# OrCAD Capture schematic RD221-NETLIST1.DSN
size A3
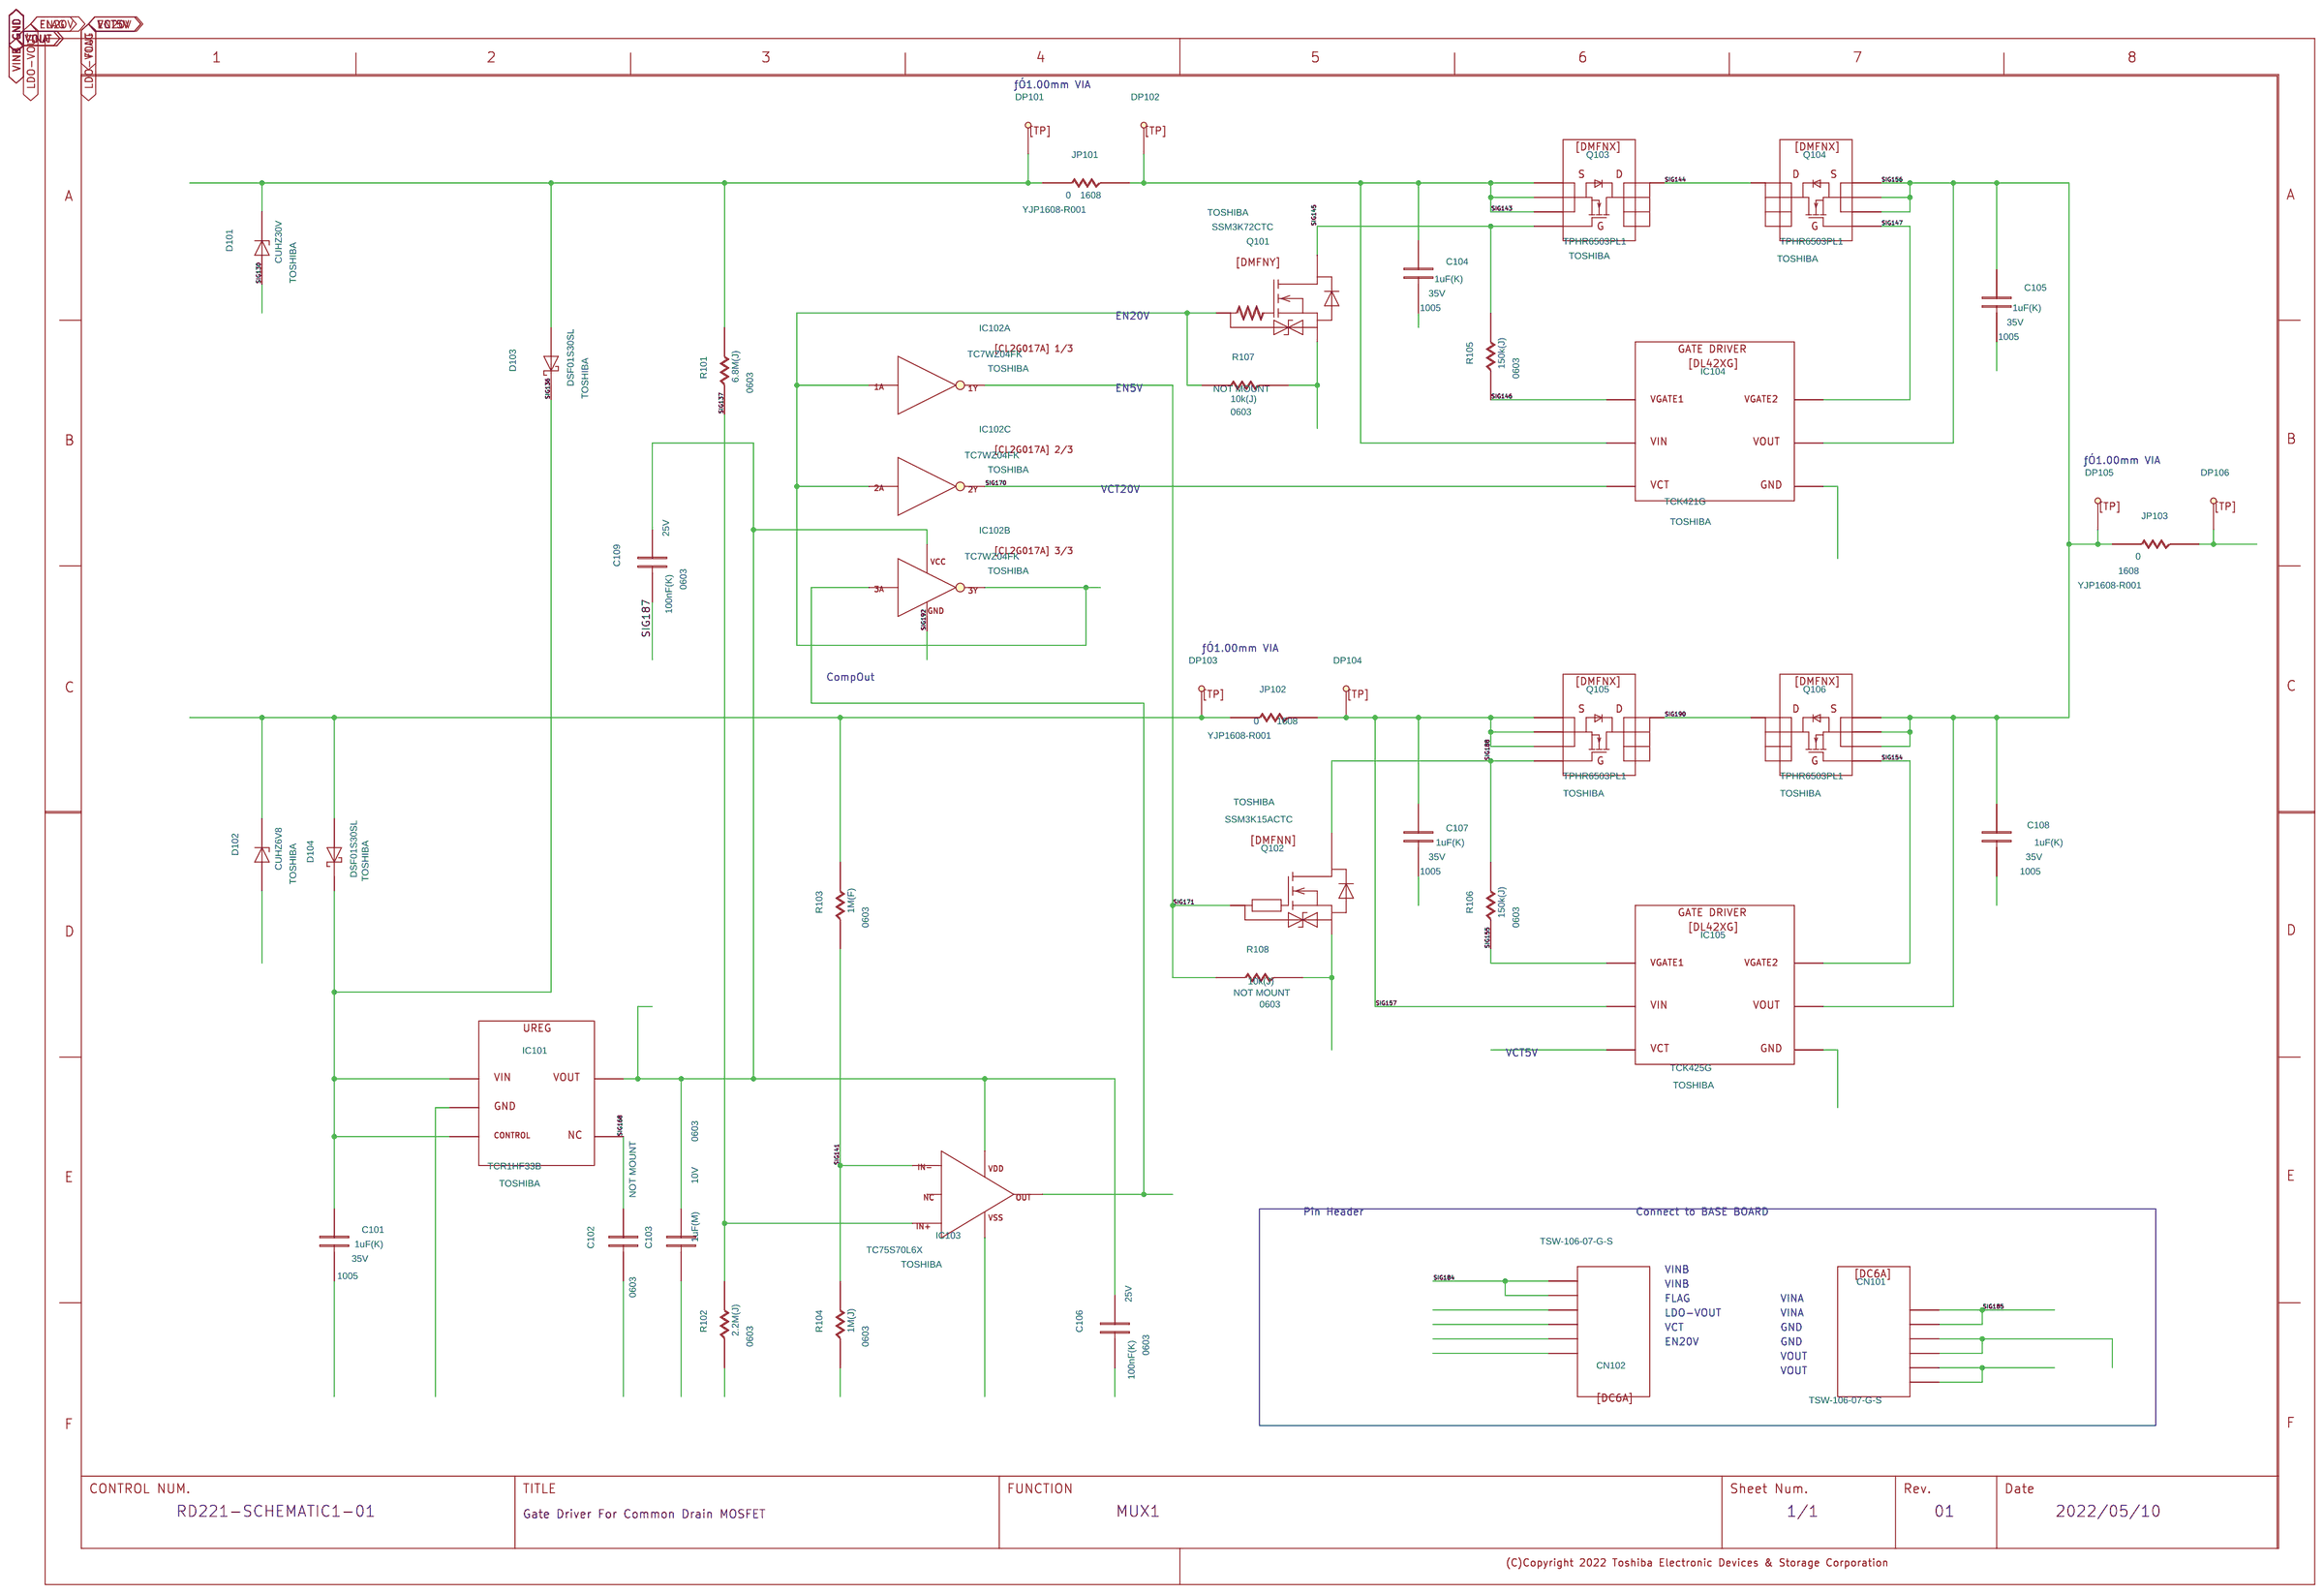
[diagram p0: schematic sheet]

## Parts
C101  DC
C102  DC
C103  DC
C104  DC
C105  DC
C106  DC
C107  DC
C108  DC
C109  DC
CN101  DC6A
CN102  DC6A
D101  DZD
D102  DZD
D103  DSBD
D104  DSBD
DP101  DTP
DP102  DTP
DP103  DTP
DP104  DTP
DP105  DTP
DP106  DTP
IC101  DL1HFXX
IC102  TC7WZ04FK_1  (sections A,B,C)
IC103  TC75S70L6X
IC104  DL42XG
IC105  DL42XG
JP101  DR
JP102  DR
JP103  DR
Q101  DMFNY
Q102  DMFNN
Q103  DMFNX
Q104  DMFNX
Q105  DMFNX
Q106  DMFNX
R101  DR
R102  DR
R103  DR
R104  DR
R105  DR
R106  DR
R107  DR
R108  DR
U?#1  WAKU_DEF100

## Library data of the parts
C101 C104 C105 C107 C108 = DC: COMP: DP0000016125; COMPONENTNAME: DP0000016125_package; FUNCN: DP0000016125; GCOUNT: 1; MAXGCOUNT: 1; OUMEPARTTYPE: C; SIZECODESMD: 1005; VAL1: 1uF(K); VAL2: 35V; VAL3: GRM155R6YA105KE11D
C102 = DC: COMP: DP0007093000; COMPONENTNAME: DP0007093000_package; FUNCN: DP0007093000; GCOUNT: 1; MAXGCOUNT: 1; NOTMOUNT: NOT MOUNT; OUMEPARTTYPE: C; SIZECODESMD: 0603; VAL1: 1uF(M); VAL2: 10V; VAL3: GRM033R61A105ME15D
C103 = DC: COMP: DP0007093000; COMPONENTNAME: DP0007093000_package; FUNCN: DP0007093000; GCOUNT: 1; MAXGCOUNT: 1; OUMEPARTTYPE: C; SIZECODESMD: 0603; VAL1: 1uF(M); VAL2: 10V; VAL3: GRM033R61A105ME15D
C106 C109 = DC: COMP: DP0000015403; COMPONENTNAME: DP0000015403_package; FUNCN: DP0000015403; GCOUNT: 1; MAXGCOUNT: 1; OUMEPARTTYPE: C; SIZECODESMD: 0603; VAL1: 100nF(K); VAL2: 25V; VAL3: GRM033R61E104KE14D
CN101 CN102 = DC6A: COMP: DP0010563000; COMPONENTNAME: DP0010563000_package; FUNCN: DP0010563000; GCOUNT: 1; MAXGCOUNT: 1; OUMEPARTTYPE: CN; VAL3: TSW-106-07-G-S
D101 = DZD: COMP: DP0010557000; COMPONENTNAME: DP0010557000_package; FUNCN: DP0010557000; GCOUNT: 1; MAXGCOUNT: 1; OUMEPARTTYPE: D; USERCOMPTEXT3: TOSHIBA; VAL1: CUHZ30V; VAL3: CUHZ30V
D102 = DZD: COMP: DP0010558000; COMPONENTNAME: DP0010558000_package; FUNCN: DP0010558000; GCOUNT: 1; MAXGCOUNT: 1; OUMEPARTTYPE: D; USERCOMPTEXT3: TOSHIBA; VAL1: CUHZ6V8; VAL3: CUHZ6V8
D103 D104 = DSBD: COMP: DP0010560000; COMPONENTNAME: DP0010560000_package; FUNCN: DP0010560000; GCOUNT: 1; MAXGCOUNT: 1; OUMEPARTTYPE: D; USERCOMPTEXT3: TOSHIBA; VAL1: DSF01S30SL; VAL3: DSF01S30SL
DP101-DP106 = DTP: COMP: DP9000817000; COMPONENTNAME: DP9000817000_package; FUNCN: DP9000817000; GCOUNT: 1; MAXGCOUNT: 1; NOTMOUNT: NOT MOUNT; OUMEPARTTYPE: TP
IC101 = DL1HFXX: COMP: DP0010559000; COMPONENTNAME: DP0010559000_package; FUNCN: DP0010559000; GCOUNT: 1; MAXGCOUNT: 1; OUMEPARTTYPE: IC; SAVEAREA0: -37394,-7797,68343,35643; SAVECOUNT: 26; UPDATEDATE: 2021/11/24; UPDATETIME: 10:48:25; UPDATEUSER: w90028dm; USERCOMPTEXT3: TOSHIBA; VAL1: TCR1HF33B; VAL3: TCR1HF33B
IC102 = TC7WZ04FK_1: COMP: DP0001429000; CaptureCellPackProp: TC7WZ04FK_1A; FUNCN: DP0001429000_1; USERCOMPTEXT3: TOSHIBA; VAL1: TC7WZ04FK; VAL3: TC7WZ04FK
IC103 = TC75S70L6X: COMP: DP0010561000; COMPONENTNAME: DP0010561000; FUNCN: DP0010561000; USERCOMPTEXT3: TOSHIBA
IC104 = DL42XG: COMP: DP0010555000; COMPONENTNAME: DP0010555000_package; FUNCN: DP0010555000; GCOUNT: 1; MAXGCOUNT: 1; OUMEPARTTYPE: IC; SAVEAREA0: 0,-2569,38100,25362; UPDATEDATE: 2021/11/09; UPDATETIME: 14:52:41; UPDATEUSER: t5459927; USERCOMPTEXT3: TOSHIBA; VAL1: TCK421G; VAL3: TCK421G
IC105 = DL42XG: COMP: DP0010556000; COMPONENTNAME: DP0010556000_package; FUNCN: DP0010556000; GCOUNT: 1; MAXGCOUNT: 1; OUMEPARTTYPE: IC; SAVEAREA0: -5715,0,43876,22860; UPDATEDATE: 2021/11/09; UPDATETIME: 13:49:24; UPDATEUSER: t5459927; USERCOMPTEXT3: TOSHIBA; VAL1: TCK425G; VAL3: TCK425G
JP101-JP103 = DR: COMP: DP0001376000; COMPCOMMENT: 0; COMPONENTNAME: DP0001376000_package; FUNCN: DP0001376000; GCOUNT: 1; MAXGCOUNT: 1; OUMEPARTTYPE: R; SIZECODESMD: 1608; VAL1: 200u(X); VAL2: 30mW; VAL3: YJP1608-R001
Q101 = DMFNY: COMP: DP0010564000; COMPONENTNAME: DP0010564000_package; FUNCN: DP0010564000; GCOUNT: 1; MAXGCOUNT: 1; OUMEPARTTYPE: Q; SAVEAREA0: -2026,0,24927,17780; UPDATEDATE: 2019/01/15; UPDATETIME: 15:53:55; UPDATEUSER: e1023210; USERCOMPTEXT3: TOSHIBA; VAL1: SSM3K72CTC; VAL3: SSM3K72CTC
Q102 = DMFNN: COMP: DP0010513000; COMPONENTNAME: DP0010513000_package; DEVICE: RN4905; DEVICENAME: RN49A1FE(TE85L); FUNCN: DP0010513000; FUNCTION: PNP&NPN_PCT; GCOUNT: 1; HETERO: RN4905_1,RN4905_2; LEVEL: STD; MAXGCOUNT: 1; OUMEPARTTYPE: Q; P/D_NUM: TOSHIBA; PARTS: 1; PKG_TYPE: 2-2J1A; SAVEAREA0: -41191,-19664,61952,27881; UPDATEDATE: 2021/11/11; UPDATETIME: 08:00:04; UPDATEUSER: t5459927; USERCOMPTEXT3: TOSHIBA; VAL1: SSM3K15ACTC; VAL3: SSM3K15ACTC
Q103-Q106 = DMFNX: COMP: DP0010562000; COMPONENTNAME: DP0010562000_package; FUNCN: DP0010562000; GCOUNT: 1; MAXGCOUNT: 1; OUMEPARTTYPE: Q; USERCOMPTEXT3: TOSHIBA; VAL1: TPHR6503PL1; VAL3: TPHR6503PL1
R101 = DR: COMP: DP0000151164; COMPONENTNAME: DP0000151164; FUNCN: DP0000151164; GCOUNT: 1; MAXGCOUNT: 1; OUMEPARTTYPE: R; SIZECODESMD: 0603; VAL1: 6.8M(J); VAL2: 50mW; VAL3: ERJ1GNJ685C
R102 = DR: COMP: DP0000151152; COMPONENTNAME: DP0000151152; FUNCN: DP0000151152; GCOUNT: 1; MAXGCOUNT: 1; OUMEPARTTYPE: R; SIZECODESMD: 0603; VAL1: 2.2M(J); VAL2: 50mW; VAL3: ERJ1GNJ225C
R103 = DR: COMP: DP0000152120; COMPONENTNAME: DP0000152120; FUNCN: DP0000152120; GCOUNT: 1; MAXGCOUNT: 1; OUMEPARTTYPE: R; SIZECODESMD: 0603; VAL1: 1M(F); VAL2: 50mW; VAL3: ERJ1GNF1004C
R104 = DR: COMP: DP0000152120; COMPONENTNAME: DP0000152120; FUNCN: DP0000152120; GCOUNT: 1; MAXGCOUNT: 1; OUMEPARTTYPE: R; SIZECODESMD: 0603; VAL1: 1M(J); VAL2: 50mW; VAL3: ERJ1GNF1004C
R105 R106 = DR: COMP: DP0000155124; COMPONENTNAME: DP0000155124; FUNCN: DP0000155124; GCOUNT: 1; MAXGCOUNT: 1; OUMEPARTTYPE: R; SIZECODESMD: 0603; VAL1: 150k(J); VAL2: 50mW; VAL3: RK73B1HTTC154J
R107 R108 = DR: COMP: DP0002867000; COMPONENTNAME: DP0002867000_package; FUNCN: DP0002867000; GCOUNT: 1; MAXGCOUNT: 1; NOTMOUNT: NOT MOUNT; OUMEPARTTYPE: R; SIZECODESMD: 0603; VAL1: 10k(J); VAL2: 50mW; VAL3: RK73B1HTTCM103J
U?#1 = WAKU_DEF100: DATE: 2022/05/10; DRAWINGNUMBER: RD221-SCHEMATIC1-01; FUNCTION: MUX1; REVISION: 01; SAVEAREA0: 148187,-66180,486823,89919; SAVECOUNT: 6; SHEETNUMBER: 1/1; TITLE: Gate Driver For Common Drain MOSFET; UPDATEDATE: 2022/05/16; UPDATETIME: 17:15:05

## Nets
GND: C101.2 C102.2 C103.2 C104.2 C105.2 C106.2 C107.2 C108.2 C109.2 CN101.3 CN101.4 D101.A D102.A IC101.2 IC102.4 IC103.2 IC104.B2 IC105.B2 Q101.S Q102.S R102.2 R104.2 R107.2 R108.2
VINA: CN101.1 CN101.2 D101.C D103.A DP101.1 JP101.1 R101.1
VINB: CN102.5 CN102.6 D102.C D104.A DP103.1 JP102.1 R103.1
EN20V: CN102.1 IC102.1 IC102.2 IC102.3 Q101.G R107.1
FLAG: CN102.4 IC102.6 IC103.1
LDO-VOUT: C103.1 C106.1 C109.1 CN102.3 IC101.5 IC102.8 IC103.6
SIG136: C101.1 D103.C D104.C IC101.1 IC101.3
SIG137: IC103.3 R101.2 R102.1
SIG141: IC103.4 R103.2 R104.1
SIG143: C104.1 DP102.1 IC104.A2 JP101.2 Q103.1 Q103.2 Q103.3
SIG144: Q103.5 Q104.5
SIG145: Q101.D Q103.4 R105.1
SIG146: IC104.A1 R105.2
SIG147: IC104.B1 Q104.4
SIG154: IC105.B1 Q106.4
SIG155: IC105.A1 R106.2
SIG156: C105.1 C108.1 DP105.1 IC104.C1 IC105.C1 JP103.1 Q104.1 Q104.2 Q104.3 Q106.1 Q106.2 Q106.3
SIG157: C107.1 DP104.1 IC105.A2 JP102.2 Q105.1 Q105.2 Q105.3
SIG168: C102.1 IC101.4
SIG170: IC102.5 IC104.C2
SIG171: IC102.7 Q102.G R108.1
SIG188: Q102.D Q105.4 R106.1
SIG190: Q105.5 Q106.5
VCT5V: CN102.2 IC105.C2
VOUT: CN101.5 CN101.6 DP106.1 JP103.2

Not connected (* = marked no-connect by the designer): IC103 5

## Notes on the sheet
- ƒÓ1.00mm VIA
- EN20V
- EN5V
- ƒÓ1.00mm VIA
- VCT20V
- ƒÓ1.00mm VIA
- CompOut
- VCT5V
- Pin Header
- Connect to BASE BOARD
- VINB
- VINB
- FLAG
- VINA
- LDO-VOUT
- VINA
- VCT
- GND
- EN20V
- GND
- VOUT
- VOUT
